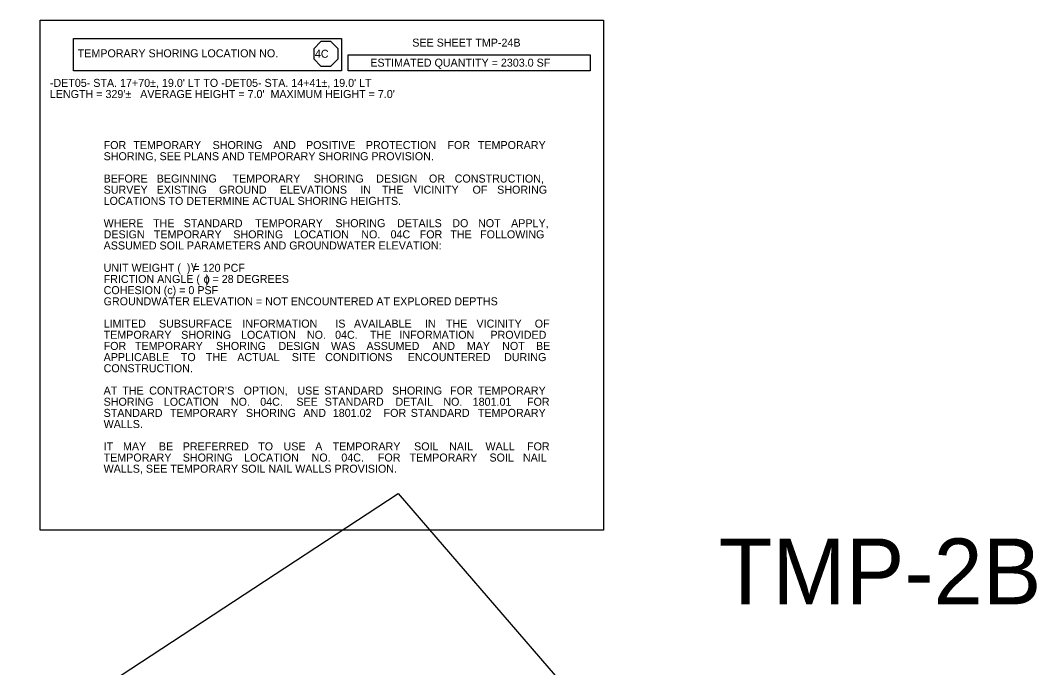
# Model space of a CAD drawing. Extents: x 2487012 to 2497594, y 369516 to 371986.
# Drawn here: x 2491299 to 2492164, y 371297 to 371848 of the extents above; entities that cross this region are included whole.
import ezdxf

# ---------------------------------------------------------------- set-up
doc = ezdxf.new("R2010")
doc.units = 0
for name, color, linetype in [('Scratch_Level_6', 7, 'Continuous'), ('TC LABEL TEMP SHORING', 7, 'Continuous'), ('TC SHEET BORDER LINE THIN', 7, 'Continuous'), ('TC SHEET LAYOUT SHAPE', 7, 'Continuous'), ('TC SHEET TEXT', 7, 'Continuous')]:
    doc.layers.add(name, color=color, linetype=linetype)

msp = doc.modelspace()

# ---------------------------------------------------------------- linework, layer by layer
at = {"layer": 'Scratch_Level_6'}
msp.add_lwpolyline([(2490800.31, 371282.27), (2490812.63, 371239.13), (2491214.19, 371433.43), (2491305.53, 371239.13), (2491620.29, 371445.42), (2491798.43, 371239.13), (2490627, 370955.22), (2490812.63, 370792.26), (2491172.91, 370953.89), (2491305.53, 370792.26), (2491661.57, 370924.58), (2491798.43, 370792.26)], dxfattribs=at)
at = {"layer": 'TC LABEL TEMP SHORING'}
for p, q in [((2491554.54, 371830.11), (2491548.46, 371823.94)), ((2491563.15, 371830.11), (2491554.54, 371830.11)), ((2491569.24, 371823.94), (2491563.15, 371830.11)), ((2491548.46, 371823.94), (2491548.46, 371815.22)), ((2491569.24, 371815.22), (2491569.24, 371823.94)), ((2491548.46, 371815.22), (2491554.54, 371809.05)), ((2491563.15, 371809.05), (2491569.24, 371815.22)), ((2491554.54, 371809.05), (2491563.15, 371809.05))]:
    msp.add_line(p, q, dxfattribs=at)
at = {"layer": 'TC SHEET BORDER LINE THIN'}
for points in [[(2491315.58, 371848.07), (2491795.03, 371848.07), (2491795.03, 371414.44), (2491315.58, 371414.44)], [(2491344.07, 371832.49), (2491572.13, 371832.49), (2491572.13, 371805.23), (2491344.07, 371805.23)], [(2491577.89, 371818.86), (2491783.67, 371818.86), (2491783.67, 371805.23), (2491577.89, 371805.23)]]:
    msp.add_lwpolyline(points, close=True, dxfattribs=at)

# ---------------------------------------------------------------- texts
at = {"layer": 'TC LABEL TEMP SHORING'}
for s, height, p in [('4C', 6.814, (2491549.46, 371816.22)), ('γ', 7.2, (2491444.03, 371636.03)), ('    ɸ', 7.2, (2491444.03, 371624.51))]:
    msp.add_text(s, height=height, dxfattribs=at).set_placement(p)
at = {"layer": 'TC SHEET BORDER LINE THIN'}
for s, height, p in [('FOR ', 6.814, (2491369.68, 371738.56)), ('TEMPORARY ', 6.814, (2491394.91, 371738.56)), ('SHORING ', 6.814, (2491462.4, 371738.56)), ('AND ', 6.814, (2491514.09, 371738.56)), ('POSITIVE ', 6.814, (2491541.87, 371738.56)), ('PROTECTION ', 6.8137, (2491592.83, 371738.56)), ('FOR ', 6.814, (2491662.24, 371738.56)), ('TEMPORARY ', 6.814, (2491688.14, 371738.56)), ('SHORING, SEE PLANS AND TEMPORARY SHORING PROVISION.', 6.8137, (2491369.68, 371729.06)), ('BEFORE ', 6.814, (2491369.68, 371710.07)), ('BEGINNING ', 6.814, (2491414.84, 371710.07)), ('TEMPORARY ', 6.814, (2491479.33, 371710.07)), ('SHORING ', 6.814, (2491548.4, 371710.07)), ('DESIGN ', 6.814, (2491601.68, 371710.07)), ('OR ', 6.814, (2491646.51, 371710.07)), ('CONSTRUCTION, ', 6.8137, (2491668.4, 371710.07)), ('SURVEY ', 6.814, (2491369.68, 371700.58)), ('EXISTING ', 6.814, (2491414.81, 371700.58)), ('GROUND ', 6.814, (2491467.85, 371700.58)), ('ELEVATIONS ', 6.8137, (2491519.57, 371700.58)), ('IN ', 6.814, (2491588.06, 371700.58)), ('THE ', 6.814, (2491606.6, 371700.58)), ('VICINITY ', 6.814, (2491633.33, 371700.58)), ('OF ', 6.814, (2491683.6, 371700.58)), ('SHORING ', 6.814, (2491704.55, 371700.58)), ('LOCATIONS TO DETERMINE ACTUAL SHORING HEIGHTS.', 6.8137, (2491369.68, 371691.08)), ('WHERE ', 6.814, (2491369.68, 371672.09)), ('THE ', 6.814, (2491411.76, 371672.09)), ('STANDARD ', 6.814, (2491437.78, 371672.09)), ('TEMPORARY ', 6.814, (2491498.56, 371672.09)), ('SHORING ', 6.814, (2491566.87, 371672.09)), ('DETAILS ', 6.814, (2491619.39, 371672.09)), ('DO ', 6.814, (2491666.38, 371672.09)), ('NOT ', 6.814, (2491688.28, 371672.09)), ('APPLY, ', 6.814, (2491716.41, 371672.09)), ('DESIGN ', 6.814, (2491369.68, 371662.6)), ('TEMPORARY ', 6.814, (2491412.39, 371662.6)), ('SHORING ', 6.814, (2491480.02, 371662.6)), ('LOCATION ', 6.814, (2491531.85, 371662.6)), ('NO. ', 6.814, (2491588.93, 371662.6)), ('04C ', 6.814, (2491613.86, 371662.6)), ('FOR ', 6.814, (2491638.64, 371662.6)), ('THE ', 6.814, (2491664.7, 371662.6)), ('FOLLOWING ', 6.814, (2491690.04, 371662.6)), ('ASSUMED SOIL PARAMETERS AND GROUNDWATER ELEVATION:', 6.8137, (2491369.68, 371653.11)), ('UNIT WEIGHT (  ) = 120 PCF', 6.8137, (2491369.68, 371634.12)), ('FRICTION ANGLE (  ) = 28 DEGREES', 6.8137, (2491369.68, 371624.62)), ('COHESION (c) = 0 PSF', 6.8137, (2491369.68, 371615.13)), ('GROUNDWATER ELEVATION = NOT ENCOUNTERED AT EXPLORED DEPTHS', 6.8137, (2491369.68, 371605.63)), ('LIMITED ', 6.814, (2491369.68, 371586.65)), ('SUBSURFACE ', 6.8137, (2491416.74, 371586.65)), ('INFORMATION ', 6.8137, (2491487.74, 371586.65)), ('IS ', 6.814, (2491566.85, 371586.65)), ('AVAILABLE ', 6.814, (2491582.68, 371586.65)), ('IN ', 6.814, (2491643.12, 371586.65)), ('THE ', 6.814, (2491660.94, 371586.65)), ('VICINITY ', 6.814, (2491686.96, 371586.65)), ('OF ', 6.814, (2491736.52, 371586.65)), ('TEMPORARY ', 6.814, (2491369.68, 371577.15)), ('SHORING ', 6.814, (2491435.68, 371577.15)), ('LOCATION ', 6.814, (2491486.56, 371577.15)), ('NO. ', 6.814, (2491542.68, 371577.15)), ('04C. ', 6.814, (2491566.65, 371577.15)), (' THE ', 6.814, (2491593.86, 371577.15)), ('INFORMATION ', 6.8137, (2491621.34, 371577.15)), ('PROVIDED ', 6.814, (2491698.82, 371577.15)), ('FOR ', 6.814, (2491369.68, 371567.66)), ('TEMPORARY ', 6.814, (2491396.36, 371567.66)), ('SHORING ', 6.814, (2491465.29, 371567.66)), ('DESIGN ', 6.814, (2491518.44, 371567.66)), ('WAS ', 6.814, (2491563.13, 371567.66)), ('ASSUMED ', 6.814, (2491593.31, 371567.66)), ('AND ', 6.814, (2491649.48, 371567.66)), ('MAY ', 6.814, (2491678.71, 371567.66)), ('NOT ', 6.814, (2491708.82, 371567.66)), ('BE ', 6.814, (2491737.58, 371567.66)), ('APPLICABLE ', 6.8137, (2491369.68, 371558.16)), ('TO ', 6.814, (2491435.37, 371558.16)), ('THE ', 6.814, (2491456.65, 371558.16)), ('ACTUAL ', 6.814, (2491483.41, 371558.16)), ('SITE ', 6.814, (2491529.82, 371558.16)), ('CONDITIONS ', 6.8137, (2491558.21, 371558.16)), ('ENCOUNTERED ', 6.8137, (2491628.5, 371558.16)), ('DURING ', 6.814, (2491710.45, 371558.16)), ('CONSTRUCTION.', 6.8137, (2491369.68, 371548.67)), ('AT ', 6.814, (2491369.68, 371529.68)), ('THE ', 6.814, (2491385.54, 371529.68)), ('CONTRACTOR’S ', 6.8137, (2491408.46, 371529.68)), ('OPTION, ', 6.814, (2491488.82, 371529.68)), ('USE ', 6.814, (2491534.59, 371529.68)), ('STANDARD ', 6.814, (2491557.41, 371529.68)), ('SHORING ', 6.814, (2491615.09, 371529.68)), ('FOR ', 6.814, (2491664.51, 371529.68)), ('TEMPORARY ', 6.814, (2491688.14, 371529.68)), ('SHORING ', 6.814, (2491369.68, 371520.18)), ('LOCATION ', 6.814, (2491420.88, 371520.18)), ('NO. ', 6.814, (2491477.99, 371520.18)), ('04C. ', 6.814, (2491502.95, 371520.18)), (' SEE ', 6.814, (2491531.15, 371520.18)), ('STANDARD ', 6.814, (2491557.88, 371520.18)), ('DETAIL ', 6.814, (2491618.01, 371520.18)), ('NO. ', 6.814, (2491658.74, 371520.18)), ('1801.01 ', 6.814, (2491683.71, 371520.18)), ('FOR ', 6.814, (2491729.96, 371520.18)), ('STANDARD ', 6.814, (2491369.68, 371510.69)), ('TEMPORARY ', 6.814, (2491426.14, 371510.69)), ('SHORING ', 6.814, (2491490.81, 371510.69)), ('AND ', 6.814, (2491539.69, 371510.69)), ('1801.02 ', 6.814, (2491564.66, 371510.69)), ('FOR ', 6.814, (2491607.91, 371510.69)), ('STANDARD ', 6.814, (2491631, 371510.69)), ('TEMPORARY ', 6.814, (2491688.14, 371510.69)), ('WALLS.', 6.814, (2491369.68, 371501.2)), ('IT ', 6.814, (2491369.68, 371482.21)), ('MAY ', 6.814, (2491386.17, 371482.21)), ('BE ', 6.814, (2491416.69, 371482.21)), ('PREFERRED ', 6.814, (2491437, 371482.21)), ('TO ', 6.814, (2491501.22, 371482.21)), ('USE ', 6.814, (2491522.78, 371482.21)), ('A ', 6.814, (2491549.74, 371482.21)), ('TEMPORARY ', 6.814, (2491564.51, 371482.21)), ('SOIL ', 6.814, (2491633.85, 371482.21)), ('NAIL ', 6.814, (2491663.67, 371482.21)), ('WALL ', 6.814, (2491694.6, 371482.21)), ('FOR ', 6.814, (2491729.96, 371482.21)), ('TEMPORARY ', 6.814, (2491369.68, 371472.71)), ('SHORING ', 6.814, (2491437, 371472.71)), ('LOCATION ', 6.814, (2491489.21, 371472.71)), ('NO. ', 6.814, (2491546.65, 371472.71)), ('04C. ', 6.814, (2491571.95, 371472.71)), (' FOR ', 6.814, (2491600.49, 371472.71)), ('TEMPORARY ', 6.814, (2491630.01, 371472.71)), ('SOIL ', 6.814, (2491698, 371472.71)), ('NAIL ', 6.814, (2491726.48, 371472.71)), ('WALLS, SEE TEMPORARY SOIL NAIL WALLS PROVISION.', 6.8137, (2491369.68, 371463.22))]:
    msp.add_text(s, height=height, dxfattribs=at).set_placement(p)
at = {"layer": 'TC SHEET LAYOUT SHAPE'}
msp.add_text('TMP-2B', height=55.996, rotation=0.00008, dxfattribs=at).set_placement((2491892.98, 371351.23))
at = {"layer": 'TC SHEET TEXT'}
for s, p in [('SEE SHEET TMP-24B', (2491632.3, 371825.69)), ('TEMPORARY SHORING LOCATION NO.', (2491347.64, 371816.62)), ('ESTIMATED QUANTITY = 2303.0 SF', (2491596.59, 371808.64)), ("-DET05- STA. 17+70±, 19.0' LT TO -DET05- STA. 14+41±, 19.0' LT", (2491323.92, 371791.45)), ("LENGTH = 329'±   AVERAGE HEIGHT = 7.0'  MAXIMUM HEIGHT = 7.0'", (2491323.92, 371781.96))]:
    msp.add_text(s, height=6.8137, dxfattribs=at).set_placement(p)

doc.saveas('drawing.dxf')
